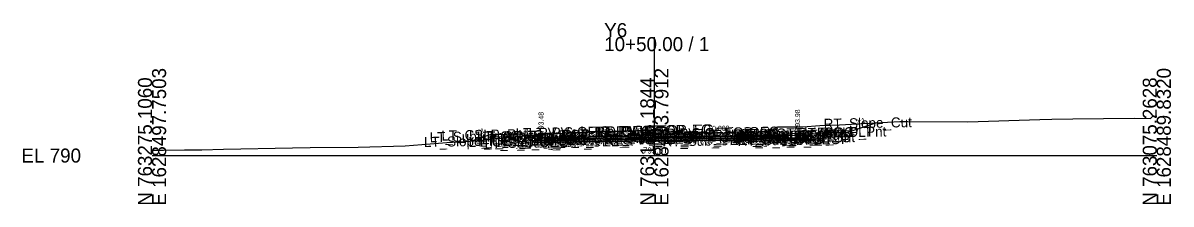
# Model space of a CAD drawing. Extents: x -26 to 203, y -10 to 6017.
# Drawn here: x -25.7 to 202.8, y 990.3 to 1026.5 of the extents above; entities that cross this region are included whole.
import ezdxf

# ---------------------------------------------------------------- set-up
doc = ezdxf.new("R2010")
doc.units = 0
for name, color, linetype in [('Default', 7, 'Continuous'), ('Exist CMT Pavement', 7, 'Continuous'), ('Exist Cross Section Cell', 7, 'Continuous'), ('Exist XS Center Line Elevation Label', 7, 'Continuous'), ('Exist XS Ground Line', 7, 'Continuous'), ('Prop CMT Conc Surface', 7, 'Continuous'), ('Prop CMT Concrete Structures', 7, 'Continuous'), ('Prop CMT Pvmt Course 1', 7, 'Continuous'), ('Prop CMT Pvmt Course 1 CG', 7, 'Continuous'), ('Prop CMT Pvmt Course 2', 7, 'Continuous'), ('Prop CMT Pvmt Course 3', 7, 'Continuous'), ('Prop CMT Pvmt Surface', 7, 'Continuous'), ('Prop CMT Pvmt Wedge Surface 1', 7, 'Continuous'), ('Prop CMT Pvmt Wedge Surface 2', 7, 'Continuous'), ('Prop CMT Pvmt Wedge Surface 3', 7, 'Continuous'), ('Prop CMT Slope Grass', 7, 'Continuous'), ('Prop CMT Subgrade Earthwork', 7, 'Continuous'), ('Prop XS Hydro Elevations', 7, 'Continuous'), ('Prop XS SE Text', 7, 'Continuous'), ('Prop XS Side Slope Text', 7, 'Continuous'), ('Scratch_Level_0', 7, 'Continuous')]:
    doc.layers.add(name, color=color, linetype=linetype)

msp = doc.modelspace()

# ---------------------------------------------------------------- linework, layer by layer
at = {"layer": 'Exist CMT Pavement'}
for points in [[(100, 1005.01), (99.9, 1005.01), (99.69, 1005.01), (99.54, 1005.01), (87.42, 1004.74)], [(100, 1005.01), (100.22, 1005), (100.3, 1005), (112.41, 1004.55)]]:
    msp.add_lwpolyline(points, dxfattribs=at)
at = {"layer": 'Exist Cross Section Cell'}
for p, q in [((100, 1000), (100, 1023.64)), ((0, 1000), (100, 1000)), ((100, 1000), (200, 1000))]:
    msp.add_line(p, q, dxfattribs=at)
at = {"layer": 'Exist XS Ground Line'}
msp.add_lwpolyline([(0, 1001.08), (2.25, 1001.1), (6.44, 1001.12), (9.94, 1001.14), (14.22, 1001.26), (27.95, 1001.54), (31.45, 1001.6), (41.06, 1001.69), (50.36, 1001.94), (58.69, 1002.62), (63.28, 1002.86), (73.02, 1003.83), (75.28, 1004.04), (76.85, 1004.19), (87.42, 1004.74), (93.08, 1004.86), (99.9, 1005.01), (108.38, 1004.67), (112.41, 1004.55), (114.27, 1004.49), (118.62, 1004.7), (120.99, 1004.81), (123.78, 1005.1), (124.16, 1005.61), (124.54, 1005.76), (128.66, 1005.76), (129.55, 1005.76), (132.96, 1006.03), (136.87, 1006.16), (143.94, 1006.53), (148.84, 1006.77), (150.45, 1006.77), (162.42, 1006.74), (176.7, 1007.19), (179.11, 1007.24), (183.3, 1007.34), (195.53, 1007.49), (198.77, 1007.38), (199.19, 1007.88), (200, 1007.88)], dxfattribs=at)
at = {"layer": 'Prop CMT Conc Surface'}
for points in [[(77.43, 1003.48), (77.43, 1003.98), (76.93, 1003.98)], [(79.43, 1003.59), (77.43, 1003.48)], [(126.5, 1004.04), (128.5, 1003.98)], [(128.5, 1003.98), (128.5, 1004.48), (129, 1004.48)]]:
    msp.add_lwpolyline(points, dxfattribs=at)
at = {"layer": 'Prop CMT Concrete Structures'}
for points in [[(79.43, 1003.59), (77.43, 1003.48), (77.43, 1003.98), (76.93, 1003.98)], [(76.93, 1003.98), (76.93, 1002.97), (79.43, 1003)], [(79.43, 1003), (79.43, 1003.59)], [(126.5, 1004.04), (128.5, 1003.98), (128.5, 1004.48), (129, 1004.48)], [(129, 1004.48), (129, 1003.48), (126.5, 1003.46)], [(126.5, 1003.46), (126.5, 1004.04)]]:
    msp.add_lwpolyline(points, dxfattribs=at)
at = {"layer": 'Prop CMT Pvmt Course 1'}
for points in [[(100, 1003.84), (79.43, 1003.59)], [(79.43, 1003.59), (79.43, 1003.34)], [(79.43, 1003.34), (100, 1003.59)], [(100, 1003.84), (126.5, 1004.04)], [(100, 1003.59), (100, 1003.84)], [(100, 1003.59), (100, 1003.84)], [(126.5, 1003.79), (100, 1003.59)], [(100, 1003.72), (100, 1003.59), (100, 1003.59)], [(100, 1003.72), (100, 1003.59), (100, 1003.59)], [(126.5, 1004.04), (126.5, 1003.79)]]:
    msp.add_lwpolyline(points, dxfattribs=at)
at = {"layer": 'Prop CMT Pvmt Course 1 CG'}
for points in [[(126.5, 1003.46), (129.5, 1003.48), (129.83, 1003.15)], [(126.5, 1003.13), (126.5, 1003.46)], [(79.43, 1003), (76.43, 1002.97), (76.1, 1002.63)], [(76.1, 1002.63), (79.43, 1002.67)], [(79.43, 1002.67), (79.43, 1003)], [(129.83, 1003.15), (126.5, 1003.13)]]:
    msp.add_lwpolyline(points, dxfattribs=at)
at = {"layer": 'Prop CMT Pvmt Course 2'}
for points in [[(100, 1003.59), (79.43, 1003.34)], [(79.43, 1003.34), (79.43, 1003)], [(79.43, 1003), (100, 1003.26)], [(100, 1003.59), (126.5, 1003.79)], [(126.5, 1003.46), (100, 1003.26)], [(126.5, 1003.79), (126.5, 1003.46)]]:
    msp.add_lwpolyline(points, dxfattribs=at)
at = {"layer": 'Prop CMT Pvmt Course 3'}
for points in [[(100, 1003.26), (79.43, 1003)], [(100, 1003.26), (126.5, 1003.46)], [(126.5, 1003.46), (126.5, 1003.13)], [(79.43, 1003), (79.43, 1002.67)], [(79.43, 1002.67), (100, 1002.93)], [(126.5, 1003.13), (100, 1002.93)]]:
    msp.add_lwpolyline(points, dxfattribs=at)
at = {"layer": 'Prop CMT Pvmt Surface'}
for points in [[(100, 1003.84), (79.43, 1003.59)], [(100, 1003.84), (126.5, 1004.04)]]:
    msp.add_lwpolyline(points, dxfattribs=at)
at = {"layer": 'Prop CMT Pvmt Wedge Surface 1'}
for points in [[(100, 1003.59), (79.43, 1003.34)], [(79.43, 1003.34), (79.43, 1003.59)], [(100, 1003.59), (126.5, 1003.79)], [(126.5, 1003.79), (126.5, 1004.04)]]:
    msp.add_lwpolyline(points, dxfattribs=at)
at = {"layer": 'Prop CMT Pvmt Wedge Surface 2'}
for points in [[(79.43, 1003.34), (79.43, 1003.59)], [(126.5, 1003.79), (126.5, 1004.04)]]:
    msp.add_lwpolyline(points, dxfattribs=at)
at = {"layer": 'Prop CMT Pvmt Wedge Surface 3'}
for points in [[(79.43, 1003), (79.43, 1003.59)], [(126.5, 1003.46), (126.5, 1004.04)]]:
    msp.add_lwpolyline(points, dxfattribs=at)
at = {"layer": 'Prop CMT Slope Grass'}
for points in [[(129, 1004.48), (138.5, 1004.67), (144.11, 1006.54)], [(76.93, 1003.98), (67.43, 1004.17), (63.59, 1002.89)]]:
    msp.add_lwpolyline(points, dxfattribs=at)
at = {"layer": 'Prop CMT Subgrade Earthwork'}
for points in [[(79.43, 1002.67), (76.1, 1002.63), (74.7, 1004.03)], [(126.5, 1003.13), (129.83, 1003.15), (131.2, 1004.52)], [(100, 1002.93), (79.43, 1002.67)], [(100, 1002.93), (126.5, 1003.13)]]:
    msp.add_lwpolyline(points, dxfattribs=at)

# ---------------------------------------------------------------- texts
at = {"layer": 'Default'}
msp.add_text('-', height=0.0001, dxfattribs=at).set_placement((0, 1000))
at = {"layer": 'Exist Cross Section Cell'}
for s, p in [('Y6', (90, 1023.64)), ('10+50.00 / 1', (90, 1020.84)), ('EL 790', (-26, 998.6))]:
    msp.add_text(s, height=2.8, dxfattribs=at).set_placement(p)
for s, p in [('E 1628497.7503', (2.8, 990)), ('E 1628493.7912', (102.8, 990)), ('E 1628489.8320', (202.8, 990)), ('N 763275.1060', (0, 990)), ('N 763175.1844', (100, 990)), ('N 763075.2628', (200, 990))]:
    msp.add_text(s, height=2.8, rotation=90, dxfattribs=at).set_placement(p)
at = {"layer": 'Exist XS Center Line Elevation Label'}
msp.add_text('795.01', height=1.2, dxfattribs=at).set_placement((97.72, 1000.41))
at = {"layer": 'Prop XS Hydro Elevations'}
for s, p in [('793.48', (77.93, 1004.48)), ('793.98', (129, 1004.98))]:
    msp.add_text(s, height=1, rotation=90, dxfattribs=at).set_placement(p)
at = {"layer": 'Prop XS SE Text'}
for s, rotation, p in [('0.012', 0.7162, (88.11, 1004.7)), ('0.008', 0.4297, (111.5, 1004.93))]:
    msp.add_text(s, height=1, rotation=rotation, dxfattribs=at).set_placement(p)
at = {"layer": 'Prop XS Side Slope Text'}
for p in [(140.31, 1006.06), (64.52, 1003.99)]:
    msp.add_text('3:1', height=1, rotation=18.4332, dxfattribs=at).set_placement(p)
at = {"layer": 'Scratch_Level_0'}
for s, p in [('LT_PV_Sub_Tie_Out', (72.4, 1003.44)), ('LT_PV_OEEOP_EG', (74.98, 1003.5)), ('RT_PV_IEEOP_EG', (88.16, 1003.77)), ('LT_PV_IEEOP_EG', (88.21, 1003.77)), ('RT_PV_Sub_Tie_Out', (97.32, 1003.25)), ('RT_PV_OEEOP_EG', (99.93, 1003.3)), ('RT_Sub_Trench_Out_DLT', (111.74, 1003.13)), ('RT_CG_Top_Face', (115.73, 1003.22)), ('RT_CG_Top_BOC', (117.26, 1003.24)), ('RT_CSLP_Pnt', (128.64, 1003.47)), ('RT_Slope_Cut', (133.72, 1005.33)), ('LT_Slope_Fill', (54.14, 1001.7)), ('LT_Sub_Trench_Out_DLT', (55.29, 1002.64)), ('LT_CSLP_Pnt', (57.63, 1002.98)), ('LT_CG1_Shelf_Out', (63.01, 1001.7)), ('LT_CG_Top_Face', (64.71, 1002.73)), ('LT_CG_Top_BOC', (65.24, 1002.75)), ('LT_CG_Bot_BOC', (65.27, 1001.74)), ('LT_CG_Top_Gut', (65.69, 1002.25)), ('LT_Sub_OEOP', (66.23, 1001.43)), ('LT_CG_Bot_IE', (69.37, 1001.8)), ('LT_Sub_OEOT', (69.53, 1001.47)), ('LT_PV2_OEOT', (69.63, 1002.14)), ('LT_PV3_OEOT', (69.63, 1001.81)), ('LT_PV1_OEOT', (70.19, 1002.4)), ('LT_Sub_OEEOP', (76.65, 1001.55)), ('LT_PV2_OEEOP', (76.74, 1002.22)), ('LT_PV3_OEEOP', (76.74, 1001.89)), ('LT_PV1_OEEOP', (77.31, 1002.36)), ('RT_PV2_IEEOP', (89.93, 1002.39)), ('RT_PV3_IEEOP', (89.93, 1002.06)), ('LT_PV2_IEEOP', (89.97, 1002.39)), ('LT_PV3_IEEOP', (89.97, 1002.06)), ('RT_PV1_IEEOP', (90.49, 1002.53)), ('LT_PV1_IEEOP', (90.54, 1002.53)), ('PV2_PGL', (93.93, 1002.47)), ('PV1_PGL', (94.49, 1002.73)), ('RT_Sub_OEEOP', (101.6, 1001.8)), ('RT_PV2_OEEOP', (101.7, 1002.47)), ('RT_PV3_OEEOP', (101.7, 1002.14)), ('RT_PV1_OEEOP', (102.26, 1002.61)), ('RT_CG1_Shelf_Out', (116.02, 1002.21)), ('RT_CG_Bot_IE', (116.38, 1002.26)), ('RT_Sub_OEOT', (116.55, 1001.93)), ('RT_PV2_OEOT', (116.64, 1002.6)), ('RT_PV3_OEOT', (116.64, 1002.26)), ('RT_CG_Top_Gut', (116.71, 1002.74)), ('RT_PV1_OEOT', (117.21, 1002.86)), ('RT_CG_Bot_BOC', (117.29, 1002.24)), ('RT_Sub_OEOP', (119.91, 1001.95))]:
    msp.add_text(s, height=2, rotation=1.1458, dxfattribs=at).set_placement(p)

doc.saveas('drawing.dxf')
